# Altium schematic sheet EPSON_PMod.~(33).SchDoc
size A4
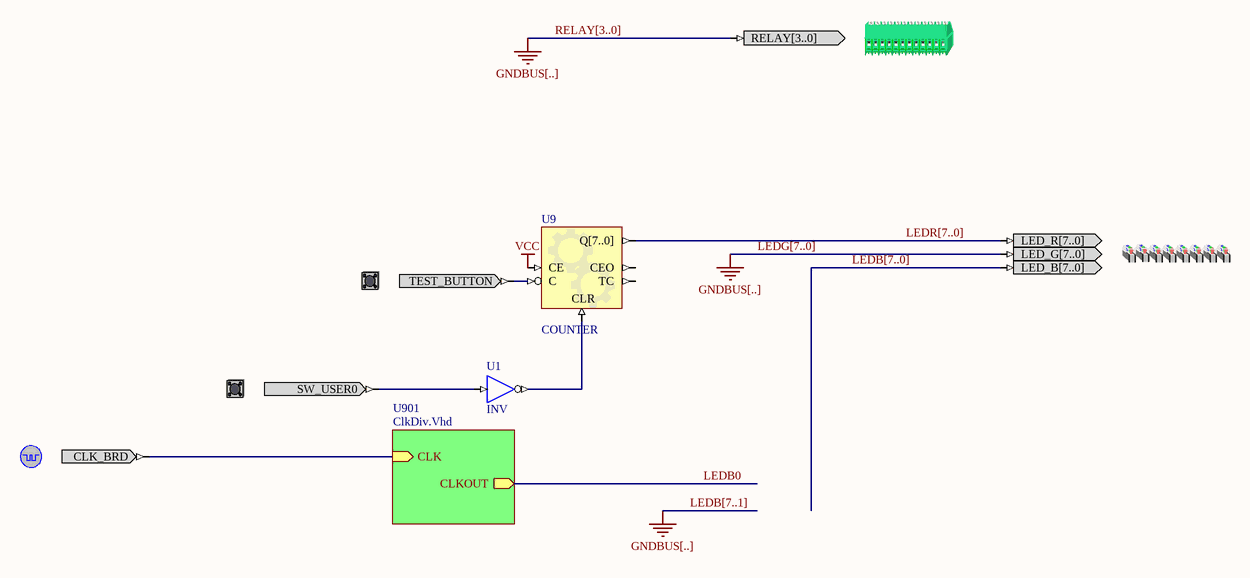
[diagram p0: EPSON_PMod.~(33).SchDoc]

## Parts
(Parts that share a designator on the sheet are numbered #1, #2 ... from top to bottom, then left to right.)
?#1  RELAYCNTR  (value not drawn)
?#2  LEDS_RGB  (value not drawn)
?#3  TEST_BUTTON  (value not drawn)
?#4  USER_BUTTON0  (value not drawn)
?#5  CLOCK_BOARD  (value not drawn)
U1  INV
U9  COUNTER

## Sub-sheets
U901 = ClkDiv.Vhd: CLK (in), CLKOUT (out)

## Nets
VCC: U9.CE
Net?#3_TEST_BUTTON: ?#3.TEST_BUTTON U9.C
Net?#4_SW_USER0: ?#4.SW_USER0 U1.I
Net?#5_CLK_BRD: ?#5.CLK_BRD ; sheet U901/CLK
NetU1_O: U1.O U9.CLR

Not connected (* = marked no-connect by the designer): ?#1 RELAY[3..0]; ?#2 LED_B[7..0] LED_G[7..0] LED_R[7..0]; U9 CEO Q[7..0] TC

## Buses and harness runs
bus LEDB[7..0]
bus LEDB[7..1]
bus LEDG[7..0]
bus LEDR[7..0]
bus RELAY[3..0]

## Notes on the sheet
- Labels drawn without touching a wire or pin: GNDBUS[..]

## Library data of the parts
?#1 = RELAYCNTR: RELAY; PortComponent: True
?#2 = LEDS_RGB: LEDS RGB; PortComponent: True
?#3 = TEST_BUTTON: Test / Reset Button; PortComponent: True
?#4 = USER_BUTTON0: Generic User Button; PortComponent: True
?#5 = CLOCK_BOARD: Global System Clock Supply; PortComponent: True
U1 = INV: Inverter; FunctionalClass: Logic Primitive; ArchiveName: GENERIC; VHDLIB_SIM: GENERIC_LIB
U9 = COUNTER: Configurable Counter; ConfiguratorName: GENERIC_COUNTER; ConfigurationParameters: {}Version[1.0]{}Type[Binary]{}SyncReset[False]{}NegativeClockEdge[True]{}FixedDirection[True]{}IsIncrement[True]{}SignalWidth[8]{}MaxValue[255]{}BusOutput[True]{}Loadable[False]{}BusInput[False]{}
